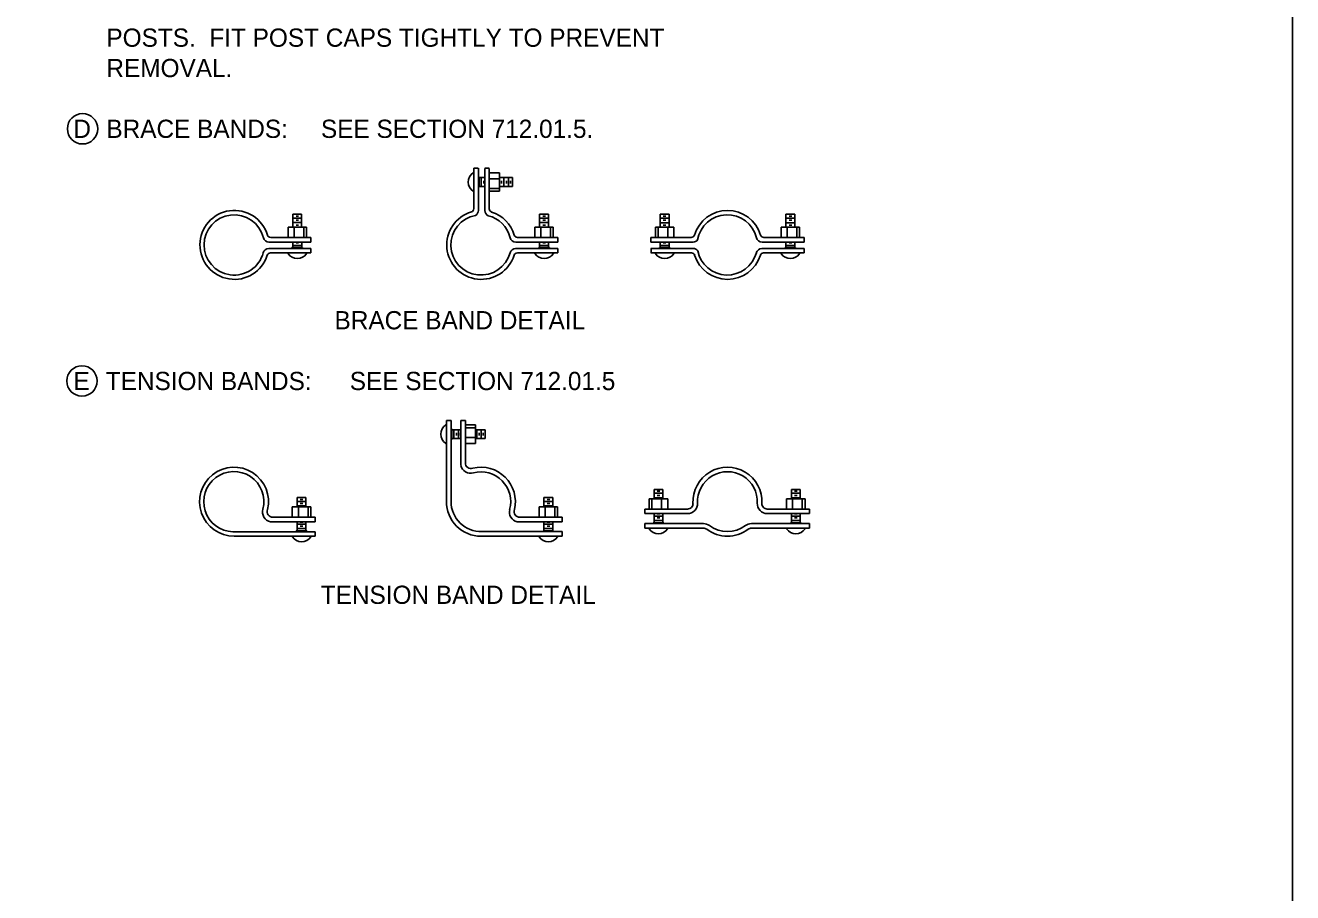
# Model space of a CAD drawing. Extents: x 49973.1 to 50021, y 49987.6 to 50015.4.
# Drawn here: x 50012.579 to 50016.75, y 49990.653 to 49993.508 of the extents above; entities that cross this region are included whole.
import ezdxf

# ---------------------------------------------------------------- set-up
doc = ezdxf.new("R2010")
doc.units = 0
doc.layers.add('Level 1', color=7, linetype='Continuous')
doc.layers.add('Level 2', color=7, linetype='Continuous')

msp = doc.modelspace()

# ---------------------------------------------------------------- linework, layer by layer
at = {"layer": 'Level 1'}
for p, q in [((50014.0546, 49993.0375), (50014.0696, 49993.0375)), ((50014.055, 49992.9049), (50014.055, 49993.0375)), ((50014.07, 49992.8989), (50014.07, 49993.0375)), ((50014.1056, 49993.0375), (50014.091, 49993.0375)), ((50014.0913, 49992.8983), (50014.0913, 49993.0373)), ((50014.1058, 49992.9043), (50014.1058, 49993.0373)), ((50014.055, 49993.0226), (50014.0525, 49993.0226)), ((50014.072, 49993.0098), (50014.07, 49993.0098)), ((50014.072, 49993.0098), (50014.072, 49992.975)), ((50014.072, 49993.0069), (50014.0913, 49993.0069)), ((50014.0792, 49993.0069), (50014.0792, 49992.9777)), ((50014.0876, 49992.9963), (50014.0876, 49992.9879)), ((50014.1056, 49993.0227), (50014.1392, 49993.0227)), ((50014.1056, 49993.0029), (50014.1392, 49993.0029)), ((50014.1392, 49993.0227), (50014.1392, 49992.9621)), ((50014.1818, 49993.0069), (50014.1392, 49993.0069)), ((50014.1458, 49992.9963), (50014.1458, 49992.9879)), ((50014.1542, 49993.0069), (50014.1542, 49992.9781)), ((50014.1624, 49992.9963), (50014.1624, 49992.9879)), ((50014.1692, 49993.0069), (50014.1692, 49992.9781)), ((50014.1756, 49992.9963), (50014.1756, 49992.9879)), ((50014.1818, 49993.0069), (50014.1818, 49992.9781)), ((50014.055, 49992.9619), (50014.0525, 49992.9619)), ((50014.072, 49992.975), (50014.07, 49992.975)), ((50014.072, 49992.9777), (50014.0913, 49992.9777)), ((50014.1056, 49992.9711), (50014.1392, 49992.9711)), ((50014.1056, 49992.9621), (50014.1392, 49992.9621)), ((50014.1818, 49992.9781), (50014.1392, 49992.9781)), ((50013.4592, 49992.8863), (50013.488, 49992.8863)), ((50013.4592, 49992.8863), (50013.4592, 49992.8437)), ((50013.4592, 49992.8733), (50013.488, 49992.8733)), ((50013.4698, 49992.8799), (50013.4782, 49992.8799)), ((50013.4698, 49992.8665), (50013.4782, 49992.8665)), ((50013.488, 49992.8863), (50013.488, 49992.8437)), ((50014.2716, 49992.8863), (50014.3004, 49992.8863)), ((50014.2716, 49992.8863), (50014.2716, 49992.8437)), ((50014.2716, 49992.8733), (50014.3004, 49992.8733)), ((50014.282, 49992.8799), (50014.2904, 49992.8799)), ((50014.282, 49992.8665), (50014.2904, 49992.8665)), ((50014.3004, 49992.8863), (50014.3004, 49992.8437)), ((50014.6976, 49992.8861), (50014.6688, 49992.8861)), ((50014.6688, 49992.8861), (50014.6688, 49992.8435)), ((50014.6976, 49992.8735), (50014.6688, 49992.8735)), ((50014.687, 49992.8799), (50014.6786, 49992.8799)), ((50014.687, 49992.8667), (50014.6786, 49992.8667)), ((50014.6976, 49992.8861), (50014.6976, 49992.8435)), ((50015.0824, 49992.8861), (50015.1112, 49992.8861)), ((50015.0824, 49992.8861), (50015.0824, 49992.8435)), ((50015.0824, 49992.8735), (50015.1112, 49992.8735)), ((50015.093, 49992.8799), (50015.1014, 49992.8799)), ((50015.093, 49992.8667), (50015.1014, 49992.8667)), ((50015.1112, 49992.8861), (50015.1112, 49992.8435)), ((50013.4434, 49992.8437), (50013.504, 49992.8437)), ((50013.4434, 49992.8098), (50013.4434, 49992.8437)), ((50013.4592, 49992.8587), (50013.488, 49992.8587)), ((50013.4632, 49992.8098), (50013.4632, 49992.8437)), ((50013.4698, 49992.8503), (50013.4782, 49992.8503)), ((50013.495, 49992.8098), (50013.495, 49992.8437)), ((50013.504, 49992.8098), (50013.504, 49992.8437)), ((50014.2556, 49992.8437), (50014.3162, 49992.8437)), ((50014.2556, 49992.8098), (50014.2556, 49992.8437)), ((50014.2716, 49992.8587), (50014.3004, 49992.8587)), ((50014.2754, 49992.8098), (50014.2754, 49992.8437)), ((50014.282, 49992.8503), (50014.2904, 49992.8503)), ((50014.3072, 49992.8098), (50014.3072, 49992.8437)), ((50014.3162, 49992.8097), (50014.3162, 49992.8437)), ((50014.7134, 49992.8435), (50014.6528, 49992.8435)), ((50014.6528, 49992.8099), (50014.6528, 49992.8435)), ((50014.6618, 49992.8099), (50014.6618, 49992.8435)), ((50014.6976, 49992.8585), (50014.6688, 49992.8585)), ((50014.687, 49992.8501), (50014.6786, 49992.8501)), ((50014.6936, 49992.8099), (50014.6936, 49992.8435)), ((50014.7134, 49992.8099), (50014.7134, 49992.8435)), ((50015.0666, 49992.8098), (50015.0666, 49992.8435)), ((50015.0666, 49992.8435), (50015.1272, 49992.8435)), ((50015.0824, 49992.8585), (50015.1112, 49992.8585)), ((50015.0864, 49992.8098), (50015.0864, 49992.8435)), ((50015.093, 49992.8501), (50015.1014, 49992.8501)), ((50015.1182, 49992.8098), (50015.1182, 49992.8435)), ((50015.1272, 49992.8098), (50015.1272, 49992.8435)), ((50013.3804, 49992.7948), (50013.519, 49992.7948)), ((50013.3865, 49992.8098), (50013.519, 49992.8098)), ((50013.4592, 49992.7765), (50013.4592, 49992.7948)), ((50013.4592, 49992.7837), (50013.488, 49992.7837)), ((50013.4698, 49992.7921), (50013.4782, 49992.7921)), ((50013.4884, 49992.7765), (50013.4884, 49992.7948)), ((50013.519, 49992.8098), (50013.519, 49992.7947)), ((50014.1928, 49992.7948), (50014.3312, 49992.7948)), ((50014.1989, 49992.8098), (50014.3312, 49992.8098)), ((50014.2716, 49992.7765), (50014.2716, 49992.7948)), ((50014.2716, 49992.7837), (50014.3004, 49992.7837)), ((50014.282, 49992.7921), (50014.2904, 49992.7921)), ((50014.3006, 49992.7765), (50014.3006, 49992.7948)), ((50014.3312, 49992.8098), (50014.3312, 49992.7948)), ((50014.7704, 49992.8098), (50014.6378, 49992.8098)), ((50014.6378, 49992.8098), (50014.6378, 49992.7948)), ((50014.7765, 49992.7948), (50014.6378, 49992.7948)), ((50014.6684, 49992.7763), (50014.6684, 49992.7948)), ((50014.6976, 49992.7835), (50014.6684, 49992.7835)), ((50014.687, 49992.7919), (50014.6786, 49992.7919)), ((50014.6976, 49992.7763), (50014.6976, 49992.7948)), ((50015.0035, 49992.7948), (50015.1422, 49992.7948)), ((50015.0095, 49992.8098), (50015.1422, 49992.8098)), ((50015.0824, 49992.7763), (50015.0824, 49992.7948)), ((50015.0824, 49992.7835), (50015.1116, 49992.7835)), ((50015.093, 49992.7919), (50015.1014, 49992.7919)), ((50015.1116, 49992.7763), (50015.1116, 49992.7948)), ((50015.1422, 49992.8098), (50015.1422, 49992.7948)), ((50013.3799, 49992.7735), (50013.5189, 49992.7735)), ((50013.3859, 49992.7589), (50013.5189, 49992.7589)), ((50013.4434, 49992.7591), (50013.4434, 49992.7567)), ((50013.4564, 49992.7765), (50013.4564, 49992.7735)), ((50013.4564, 49992.7765), (50013.4912, 49992.7765)), ((50013.4912, 49992.7765), (50013.4912, 49992.7735)), ((50013.5042, 49992.7591), (50013.5042, 49992.7567)), ((50013.5186, 49992.7591), (50013.5186, 49992.7735)), ((50014.1923, 49992.7735), (50014.331, 49992.7735)), ((50014.1983, 49992.7589), (50014.331, 49992.7589)), ((50014.256, 49992.7589), (50014.256, 49992.7566)), ((50014.2688, 49992.7765), (50014.2688, 49992.7735)), ((50014.2688, 49992.7765), (50014.3036, 49992.7765)), ((50014.3036, 49992.7765), (50014.3036, 49992.7735)), ((50014.3167, 49992.7589), (50014.3167, 49992.7566)), ((50014.331, 49992.7589), (50014.331, 49992.7735)), ((50014.777, 49992.7735), (50014.6381, 49992.7735)), ((50014.7711, 49992.7589), (50014.6381, 49992.7589)), ((50014.6382, 49992.7589), (50014.6382, 49992.7737)), ((50014.6526, 49992.7589), (50014.6526, 49992.7566)), ((50014.6658, 49992.7763), (50014.6658, 49992.7735)), ((50014.7005, 49992.7763), (50014.6658, 49992.7763)), ((50014.7005, 49992.7763), (50014.7005, 49992.7735)), ((50014.7134, 49992.7589), (50014.7134, 49992.7566)), ((50015.0029, 49992.7735), (50015.1418, 49992.7735)), ((50015.0089, 49992.7589), (50015.1418, 49992.7589)), ((50015.0666, 49992.7589), (50015.0666, 49992.7566)), ((50015.0794, 49992.7763), (50015.1142, 49992.7763)), ((50015.0794, 49992.7763), (50015.0794, 49992.7735)), ((50015.1142, 49992.7763), (50015.1142, 49992.7735)), ((50015.1273, 49992.7589), (50015.1273, 49992.7566)), ((50015.1418, 49992.7589), (50015.1418, 49992.7735)), ((50013.9648, 49991.9407), (50013.9648, 49992.2075)), ((50013.9648, 49992.2075), (50013.98, 49992.2075)), ((50013.98, 49991.9407), (50013.98, 49992.2075)), ((50014.0122, 49992.0599), (50014.0122, 49992.2075)), ((50014.0272, 49992.2075), (50014.0122, 49992.2075)), ((50014.0272, 49992.0683), (50014.0272, 49992.2075)), ((50013.9648, 49992.1928), (50013.9623, 49992.1928)), ((50013.9822, 49992.1796), (50013.98, 49992.1796)), ((50013.9822, 49992.1449), (50013.9822, 49992.1796)), ((50013.9822, 49992.1771), (50014.0122, 49992.1771)), ((50013.9894, 49992.1479), (50013.9894, 49992.1771)), ((50013.9978, 49992.1583), (50013.9978, 49992.1667)), ((50014.004, 49992.1479), (50014.004, 49992.1771)), ((50014.011, 49992.1583), (50014.011, 49992.1667)), ((50014.0272, 49992.1927), (50014.061, 49992.1927)), ((50014.0272, 49992.1835), (50014.061, 49992.1835)), ((50014.0272, 49992.1519), (50014.061, 49992.1519)), ((50014.061, 49992.1319), (50014.061, 49992.1927)), ((50014.092, 49992.1767), (50014.061, 49992.1767)), ((50014.0644, 49992.1479), (50014.0644, 49992.1767)), ((50014.0722, 49992.1583), (50014.0722, 49992.1667)), ((50014.079, 49992.1479), (50014.079, 49992.1767)), ((50014.0856, 49992.1583), (50014.0856, 49992.1667)), ((50014.092, 49992.1479), (50014.092, 49992.1767)), ((50013.9648, 49992.1321), (50013.9623, 49992.1321)), ((50013.9822, 49992.1449), (50013.98, 49992.1449)), ((50013.9822, 49992.1479), (50014.0122, 49992.1479)), ((50014.0272, 49992.1319), (50014.061, 49992.1319)), ((50014.092, 49992.1479), (50014.061, 49992.1479)), ((50013.4732, 49991.9543), (50013.5022, 49991.9543)), ((50013.4732, 49991.9543), (50013.4732, 49991.9231)), ((50013.4836, 49991.9479), (50013.4924, 49991.9479)), ((50013.5022, 49991.9543), (50013.5022, 49991.9231)), ((50014.2858, 49991.9543), (50014.3146, 49991.9543)), ((50014.2858, 49991.9543), (50014.2858, 49991.9231)), ((50014.2962, 49991.9479), (50014.3046, 49991.9479)), ((50014.3146, 49991.9543), (50014.3146, 49991.9231)), ((50014.6932, 49991.9499), (50014.6322, 49991.9499)), ((50014.6322, 49991.9158), (50014.6322, 49991.9499)), ((50014.6412, 49991.9158), (50014.6412, 49991.9499)), ((50014.6772, 49991.9807), (50014.6482, 49991.9807)), ((50014.6482, 49991.9807), (50014.6482, 49991.9499)), ((50014.6772, 49991.9679), (50014.6482, 49991.9679)), ((50014.6772, 49991.9531), (50014.6482, 49991.9531)), ((50014.6668, 49991.9743), (50014.658, 49991.9743)), ((50014.6668, 49991.9611), (50014.658, 49991.9611)), ((50014.673, 49991.9158), (50014.673, 49991.9499)), ((50014.6772, 49991.9807), (50014.6772, 49991.9499)), ((50014.6932, 49991.9158), (50014.6932, 49991.9499)), ((50015.0844, 49991.9158), (50015.0844, 49991.9499)), ((50015.0844, 49991.9499), (50015.1452, 49991.9499)), ((50015.1002, 49991.9807), (50015.1294, 49991.9807)), ((50015.1002, 49991.9807), (50015.1002, 49991.9499)), ((50015.1002, 49991.9679), (50015.1294, 49991.9679)), ((50015.1002, 49991.9531), (50015.1294, 49991.9531)), ((50015.1044, 49991.9158), (50015.1044, 49991.9499)), ((50015.1108, 49991.9743), (50015.1194, 49991.9743)), ((50015.1108, 49991.9611), (50015.1194, 49991.9611)), ((50015.1294, 49991.9807), (50015.1294, 49991.9499)), ((50015.1362, 49991.9158), (50015.1362, 49991.9499)), ((50015.1452, 49991.9158), (50015.1452, 49991.9499)), ((50013.4572, 49991.8895), (50013.4572, 49991.9231)), ((50013.4572, 49991.9231), (50013.5182, 49991.9231)), ((50013.4732, 49991.9411), (50013.5022, 49991.9411)), ((50013.4732, 49991.9267), (50013.5022, 49991.9267)), ((50013.4774, 49991.8895), (50013.4774, 49991.9231)), ((50013.4836, 49991.9343), (50013.4924, 49991.9343)), ((50013.5092, 49991.8895), (50013.5092, 49991.9231)), ((50013.5182, 49991.8895), (50013.5182, 49991.9231)), ((50014.2698, 49991.8895), (50014.2698, 49991.9231)), ((50014.2698, 49991.9231), (50014.3304, 49991.9231)), ((50014.2858, 49991.9411), (50014.3146, 49991.9411)), ((50014.2858, 49991.9267), (50014.3146, 49991.9267)), ((50014.2896, 49991.8895), (50014.2896, 49991.9231)), ((50014.2962, 49991.9343), (50014.3046, 49991.9343)), ((50014.3214, 49991.8895), (50014.3214, 49991.9231)), ((50014.3304, 49991.8895), (50014.3304, 49991.9231)), ((50014.6176, 49991.9158), (50014.6176, 49991.9008)), ((50014.7584, 49991.9158), (50014.6176, 49991.9158)), ((50015.021, 49991.9158), (50015.16, 49991.9158)), ((50015.16, 49991.9158), (50015.16, 49991.9008)), ((50013.3852, 49991.8743), (50013.5328, 49991.8743)), ((50013.3936, 49991.8895), (50013.5328, 49991.8895)), ((50013.4734, 49991.8443), (50013.4734, 49991.8743)), ((50013.4734, 49991.8663), (50013.5022, 49991.8663)), ((50013.4836, 49991.8731), (50013.4924, 49991.8731)), ((50013.4836, 49991.8599), (50013.4924, 49991.8599)), ((50013.5022, 49991.8443), (50013.5022, 49991.8743)), ((50013.5328, 49991.8895), (50013.5328, 49991.8743)), ((50014.1976, 49991.8743), (50014.3452, 49991.8743)), ((50014.2062, 49991.8895), (50014.3452, 49991.8895)), ((50014.2858, 49991.8443), (50014.2858, 49991.8743)), ((50014.2858, 49991.8663), (50014.3148, 49991.8663)), ((50014.2962, 49991.8731), (50014.3046, 49991.8731)), ((50014.2962, 49991.8599), (50014.3046, 49991.8599)), ((50014.3148, 49991.8443), (50014.3148, 49991.8743)), ((50014.3452, 49991.8895), (50014.3452, 49991.8743)), ((50014.7584, 49991.9008), (50014.6176, 49991.9008)), ((50014.6176, 49991.8532), (50014.6176, 49991.8682)), ((50014.8107, 49991.8682), (50014.6176, 49991.8682)), ((50014.6801, 49991.8711), (50014.6453, 49991.8711)), ((50014.6453, 49991.8711), (50014.6453, 49991.8682)), ((50014.6482, 49991.8711), (50014.6482, 49991.9008)), ((50014.677, 49991.8927), (50014.6482, 49991.8927)), ((50014.677, 49991.8783), (50014.6482, 49991.8783)), ((50014.6668, 49991.8999), (50014.658, 49991.8999)), ((50014.6668, 49991.8867), (50014.658, 49991.8867)), ((50014.677, 49991.8711), (50014.677, 49991.9008)), ((50014.6801, 49991.8711), (50014.6801, 49991.8682)), ((50014.9687, 49991.8682), (50015.1599, 49991.8682)), ((50015.021, 49991.9008), (50015.16, 49991.9008)), ((50015.0975, 49991.8711), (50015.1322, 49991.8711)), ((50015.0975, 49991.8711), (50015.0975, 49991.8682)), ((50015.1006, 49991.8711), (50015.1006, 49991.9008)), ((50015.1006, 49991.8927), (50015.1294, 49991.8927)), ((50015.1006, 49991.8783), (50015.1294, 49991.8783)), ((50015.1108, 49991.8999), (50015.1194, 49991.8999)), ((50015.1108, 49991.8867), (50015.1194, 49991.8867)), ((50015.1294, 49991.8711), (50015.1294, 49991.9008)), ((50015.1322, 49991.8711), (50015.1322, 49991.8682)), ((50015.16, 49991.8535), (50015.16, 49991.8687)), ((50013.262, 49991.8415), (50013.5328, 49991.8415)), ((50013.2662, 49991.8271), (50013.5328, 49991.8271)), ((50013.4577, 49991.8271), (50013.4577, 49991.8243)), ((50013.4705, 49991.8443), (50013.5053, 49991.8443)), ((50013.4705, 49991.8443), (50013.4705, 49991.8415)), ((50013.4734, 49991.8515), (50013.5022, 49991.8515)), ((50013.5053, 49991.8443), (50013.5053, 49991.8415)), ((50013.5184, 49991.8271), (50013.5184, 49991.8243)), ((50013.5328, 49991.8271), (50013.5328, 49991.8415)), ((50014.0754, 49991.8423), (50014.3452, 49991.8423)), ((50014.0784, 49991.8271), (50014.3452, 49991.8271)), ((50014.2701, 49991.8271), (50014.2701, 49991.8243)), ((50014.2829, 49991.8443), (50014.3177, 49991.8443)), ((50014.2829, 49991.8443), (50014.2829, 49991.8423)), ((50014.2858, 49991.8515), (50014.3148, 49991.8515)), ((50014.3177, 49991.8443), (50014.3177, 49991.8423)), ((50014.3308, 49991.8271), (50014.3308, 49991.8243)), ((50014.3452, 49991.8271), (50014.3452, 49991.8423)), ((50014.8107, 49991.8532), (50014.6176, 49991.8532)), ((50014.6322, 49991.8532), (50014.6322, 49991.8507)), ((50014.6929, 49991.8532), (50014.6929, 49991.8507)), ((50014.9687, 49991.8532), (50015.1599, 49991.8532)), ((50015.0846, 49991.8532), (50015.0846, 49991.8507)), ((50015.1454, 49991.8532), (50015.1454, 49991.8507))]:
    msp.add_line(p, q, dxfattribs=at)
msp.add_lwpolyline([(49999.3835, 49998.9992), (50016.7501, 49998.9992), (50016.7501, 49987.7988), (49999.3835, 49987.7988)], close=True, dxfattribs=at)
for centre, radius, start, end in [((50014.0728, 49992.9922), 0.0365, 123.7236, 236.2764), ((50014.0437, 49992.9049), 0.0113, 286.5993, 0), ((50014.1171, 49992.9043), 0.0113, 180, 252.4052), ((50013.267, 49992.7854), 0.1135, 16.5993, 342.4052), ((50013.2661, 49992.7852), 0.0991, 13.9263, 345.031), ((50014.0793, 49992.7854), 0.1135, 106.5993, 342.4052), ((50014.0785, 49992.7852), 0.0991, 100.4135, 345.031), ((50014.0512, 49992.8989), 0.0188, 299.8891, 0), ((50014.11, 49992.8983), 0.0188, 180, 244.2952), ((50014.0785, 49992.7852), 0.0991, 13.9263, 76.3363), ((50014.0793, 49992.7854), 0.1135, 16.5993, 72.3791), ((50014.89, 49992.7854), 0.1135, 16.5993, 163.3762), ((50014.8891, 49992.7852), 0.0991, 13.9263, 170.054), ((50013.3804, 49992.8135), 0.0188, 193.9263, 270), ((50013.3865, 49992.821), 0.0113, 196.5993, 270), ((50014.1928, 49992.8135), 0.0188, 193.9263, 270), ((50014.1989, 49992.821), 0.0113, 196.5993, 270), ((50014.7704, 49992.821), 0.0113, 270, 343.4007), ((50014.7765, 49992.8135), 0.0188, 270, 323.1668), ((50015.0035, 49992.8135), 0.0188, 193.9263, 270), ((50015.0095, 49992.821), 0.0113, 196.5993, 270), ((50013.3799, 49992.7547), 0.0188, 90, 165.031), ((50013.3859, 49992.7477), 0.0113, 90, 162.4052), ((50013.4739, 49992.7768), 0.0365, 213.7236, 326.2764), ((50014.1923, 49992.7547), 0.0188, 90, 165.031), ((50014.1983, 49992.7477), 0.0113, 90, 162.4052), ((50014.2863, 49992.7768), 0.0365, 213.7236, 326.2764), ((50014.683, 49992.7768), 0.0365, 213.7236, 326.2764), ((50014.7711, 49992.7477), 0.0113, 17.5948, 90), ((50014.777, 49992.7547), 0.0188, 37.8362, 90), ((50014.89, 49992.7854), 0.1135, 197.5948, 342.4052), ((50014.8891, 49992.7852), 0.0991, 191.0172, 345.031), ((50015.0029, 49992.7547), 0.0188, 90, 165.031), ((50015.0089, 49992.7477), 0.0113, 90, 162.4052), ((50015.097, 49992.7768), 0.0365, 213.7236, 326.2764), ((50013.9826, 49992.1624), 0.0365, 123.7236, 236.2764), ((50014.0452, 49992.0674), 0.0181, 177.2212, 291.9983), ((50013.2658, 49991.9402), 0.1135, 346.6398, 270.2116), ((50013.2649, 49991.9402), 0.0991, 345.5706, 268.3509), ((50014.044, 49992.0664), 0.0326, 191.9857, 286.8943), ((50014.0782, 49991.9402), 0.1135, 346.6398, 103.3647), ((50014.0782, 49991.9402), 0.0981, 344.8526, 104.5969), ((50014.8897, 49991.9404), 0.1135, 357.1253, 182.8747), ((50014.8897, 49991.9404), 0.0985, 357.1253, 182.8747), ((50013.3921, 49991.906), 0.0326, 163.1057, 258.0143), ((50013.393, 49991.9072), 0.0181, 158.0017, 272.7788), ((50014.0782, 49991.9402), 0.1135, 179.8068, 270.2116), ((50014.0782, 49991.9402), 0.0981, 179.7763, 271.5471), ((50014.2044, 49991.906), 0.0326, 164.8526, 258.0143), ((50014.2054, 49991.9072), 0.0181, 158.0017, 272.7788), ((50014.7584, 49991.9338), 0.033, 270, 2.8747), ((50014.7584, 49991.9338), 0.018, 270, 2.8747), ((50015.021, 49991.9338), 0.033, 177.1253, 270), ((50015.021, 49991.9338), 0.018, 177.1253, 270), ((50014.8107, 49991.8352), 0.033, 53.0884, 90), ((50014.8897, 49991.9404), 0.0985, 233.0884, 306.9116), ((50014.9687, 49991.8352), 0.033, 90, 126.9116), ((50013.4881, 49991.8446), 0.0365, 213.7236, 326.2764), ((50014.3004, 49991.8446), 0.0365, 213.7236, 326.2764), ((50014.6625, 49991.871), 0.0365, 213.7236, 326.2764), ((50014.8107, 49991.8352), 0.018, 53.0884, 90), ((50014.8897, 49991.9404), 0.1135, 233.0884, 306.9116), ((50014.9687, 49991.8352), 0.018, 90, 126.9116), ((50015.115, 49991.871), 0.0365, 213.7236, 326.2764)]:
    msp.add_arc(centre, radius, start, end, dxfattribs=at)
at = {"layer": 'Level 2'}
for centre in [(50012.7672, 49993.1675), (50012.7651, 49992.3375)]:
    msp.add_circle(centre, 0.05, dxfattribs=at)

# ---------------------------------------------------------------- texts
for s, p in [('POSTS.  FIT POST CAPS TIGHTLY TO PREVENT', (50012.8455, 49993.4375)), ('REMOVAL.', (50012.8455, 49993.3375)), ('D', (50012.7368, 49993.1375)), ('BRACE BANDS:', (50012.8455, 49993.1375)), ('  SEE SECTION 712.01.5.', (50013.5072, 49993.1375)), ('BRACE BAND DETAIL', (50013.5965, 49992.5075)), ('E', (50012.7371, 49992.3075)), ('TENSION BANDS:', (50012.8435, 49992.3075)), ('  SEE SECTION 712.01.5', (50013.602, 49992.3075)), ('TENSION BAND DETAIL', (50013.5512, 49991.6038))]:
    msp.add_text(s, height=0.06, dxfattribs=at).set_placement(p)

doc.saveas('drawing.dxf')
